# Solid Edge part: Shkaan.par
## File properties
Author: Türk
Template: Iso Part.par
Last saved by: Türk
Revision: 14
Application: Solid Edge
Accuracy: 0,990
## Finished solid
Body 1: solid body, 9 faces, 9 edges, 0 vertices.
  Faces by surface: cylinder 4, plane 4, torus 1
  Edges by curve: circle 9
Bounding box of the edges (mm; curved faces can reach further): 60.000 x 15.000 x 60.000, from (-30, 0, -30) to (30, 15, 30).
Cylindrical faces by radius (mm): R6.25 x1, R22.5 x1, R25 x1, R30 x1
Toroidal faces (ring radius, tube radius in mm): R16 r14 x1
Planar faces by outward normal: +y 1, -y 3
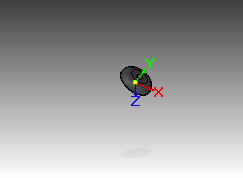
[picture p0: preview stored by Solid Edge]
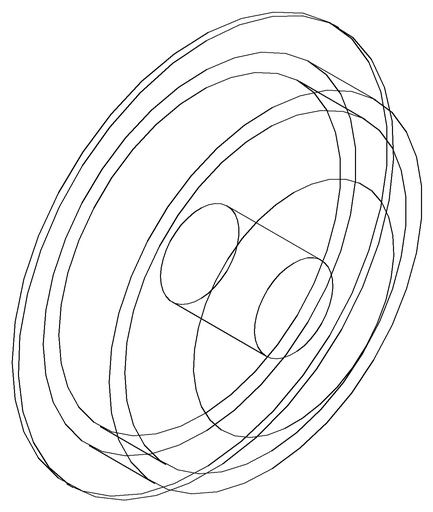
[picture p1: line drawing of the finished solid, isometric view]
